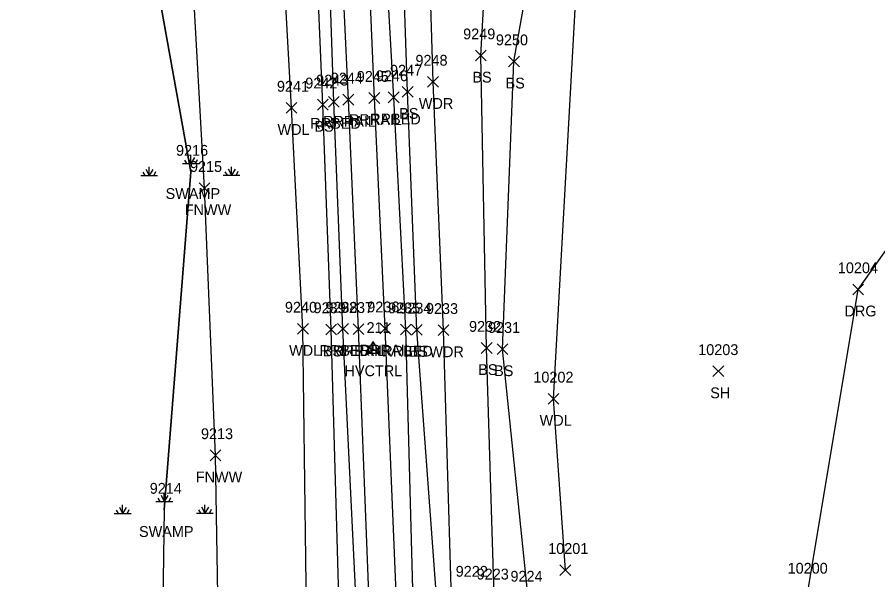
# Model space of a CAD drawing. Extents: x 1769141 to 1770911, y 735471 to 741449.
# Drawn here: x 1770233.4 to 1770392.9, y 738326.8 to 738431 of the extents above; entities that cross this region are included whole.
import ezdxf

# ---------------------------------------------------------------- set-up
doc = ezdxf.new("R2010")
doc.units = 0
for name, color, linetype in [('C_A', 7, 'Continuous'), ('C_I', 7, 'Continuous'), ('CPSM', 7, 'Continuous'), ('L_A', 7, 'Continuous'), ('L_I', 7, 'Continuous'), ('L_TIC', 7, 'Continuous'), ('LAWA', 7, 'Continuous'), ('LELB', 7, 'Continuous'), ('LFNC', 7, 'Continuous'), ('LSOGP', 7, 'Continuous'), ('LWET', 7, 'Continuous'), ('R_A', 7, 'Continuous'), ('R_I', 7, 'Continuous'), ('R_TIC', 7, 'Continuous'), ('RDG', 7, 'Continuous'), ('RR', 7, 'Continuous'), ('RRB', 7, 'Continuous'), ('U_I', 7, 'Continuous')]:
    doc.layers.add(name, color=color, linetype=linetype)

msp = doc.modelspace()

# ---------------------------------------------------------------- linework, layer by layer
at = {"layer": 'CPSM'}
for p, q in [((1770298.12, 738368.83), (1770299.37, 738371)), ((1770300.62, 738368.83), (1770299.37, 738371)), ((1770299.37, 738369.55), (1770299.37, 738371)), ((1770298.12, 738368.83), (1770299.37, 738369.55)), ((1770298.12, 738368.83), (1770300.62, 738368.83)), ((1770299.37, 738369.55), (1770299.37, 738369.55)), ((1770299.37, 738369.55), (1770300.62, 738368.83))]:
    msp.add_line(p, q, dxfattribs=at)
at = {"layer": 'L_TIC'}
for points in [[(1770318.32, 738422.93), (1770320.32, 738424.93)], [(1770320.32, 738422.93), (1770318.32, 738424.93)], [(1770324.47, 738421.83), (1770326.47, 738423.83)], [(1770326.47, 738421.83), (1770324.47, 738423.83)], [(1770309.47, 738418.05), (1770311.47, 738420.05)], [(1770311.47, 738418.05), (1770309.47, 738420.05)], [(1770304.76, 738416.21), (1770306.76, 738418.21)], [(1770306.76, 738416.21), (1770304.76, 738418.21)], [(1770283.23, 738413.23), (1770285.23, 738415.23)], [(1770285.23, 738413.23), (1770283.23, 738415.23)], [(1770289.05, 738413.83), (1770291.05, 738415.83)], [(1770291.05, 738413.83), (1770289.05, 738415.83)], [(1770267.11, 738398.37), (1770269.11, 738400.37)], [(1770269.11, 738398.37), (1770267.11, 738400.37)], [(1770285.37, 738372.32), (1770287.37, 738374.32)], [(1770287.37, 738372.32), (1770285.37, 738374.32)], [(1770290.6, 738372.21), (1770292.6, 738374.21)], [(1770292.6, 738372.21), (1770290.6, 738374.21)], [(1770306.48, 738372.15), (1770308.48, 738374.15)], [(1770308.48, 738372.15), (1770306.48, 738374.15)], [(1770311.42, 738372.07), (1770313.42, 738374.07)], [(1770313.42, 738372.07), (1770311.42, 738374.07)], [(1770319.4, 738368.77), (1770321.4, 738370.77)], [(1770321.4, 738368.77), (1770319.4, 738370.77)], [(1770322.35, 738368.56), (1770324.35, 738370.56)], [(1770324.35, 738368.56), (1770322.35, 738370.56)], [(1770362.35, 738364.46), (1770364.35, 738366.46)], [(1770364.35, 738364.46), (1770362.35, 738366.46)], [(1770331.81, 738359.37), (1770333.81, 738361.37)], [(1770333.81, 738359.37), (1770331.81, 738361.37)], [(1770269.16, 738348.89), (1770271.16, 738350.89)], [(1770271.16, 738348.89), (1770269.16, 738350.89)], [(1770333.99, 738327.63), (1770335.99, 738329.63)], [(1770335.99, 738327.63), (1770333.99, 738329.63)]]:
    msp.add_lwpolyline(points, dxfattribs=at)
at = {"layer": 'LAWA'}
for points in [[(1770290.87, 738210.89), (1770288.63, 738250.64), (1770288.03, 738279.05), (1770287.09, 738316.52), (1770286.37, 738373.32), (1770284.23, 738414.23), (1770281.88, 738456.63), (1770278.67, 738493.65), (1770276.84, 738534.04), (1770275.57, 738566.34), (1770269.92, 738609.96), (1770271.4, 738639.13), (1770266.81, 738683.22), (1770266.67, 738720.45), (1770266.46, 738767.63)], [(1770315.31, 737855.3), (1770316.28, 737876.24), (1770318.08, 737906.16), (1770319.03, 737952.94), (1770319.51, 737991.64), (1770322.73, 738039.36), (1770319.98, 738085.11), (1770320.24, 738127.38), (1770319.97, 738169.49), (1770317.68, 738213.18), (1770316.02, 738251.23), (1770320.47, 738275.34), (1770313.94, 738321.19), (1770312.42, 738373.07), (1770310.47, 738419.05), (1770309.28, 738459.52), (1770309.11, 738496.14), (1770304.45, 738533.38), (1770304.4, 738567.19), (1770302.72, 738608.9), (1770310.17, 738610.98)], [(1770334.99, 738328.63), (1770332.81, 738360.37), (1770337.6, 738446.97), (1770400.36, 738434.35)]]:
    msp.add_lwpolyline(points, dxfattribs=at)
at = {"layer": 'LELB'}
for points in [[(1770313.1, 738041.42), (1770314.65, 738083.84), (1770313.8, 738128.25), (1770314.4, 738170.05), (1770312.34, 738212.97), (1770312.21, 738250.53), (1770315.19, 738274.63), (1770311.43, 738319.54), (1770307.48, 738373.15), (1770305.76, 738417.21), (1770304.29, 738459.21), (1770301.19, 738494.77), (1770301.03, 738535.15), (1770299.09, 738567.61), (1770297.92, 738610.57), (1770296.26, 738639.11), (1770291.84, 738684.86), (1770290.03, 738722.63), (1770290.09, 738765.93)], [(1770294.4, 738212.07), (1770294.88, 738249.38), (1770293.51, 738277.71), (1770293.17, 738317.26), (1770291.6, 738373.21), (1770290.05, 738414.83), (1770288.24, 738457.21), (1770285.83, 738494.21), (1770284.22, 738534.7), (1770282.04, 738566.65), (1770280.54, 738611.07), (1770279.02, 738639.53), (1770277.04, 738683.67), (1770274.8, 738722.5), (1770272.74, 738765.19)], [(1770326.03, 738235.15), (1770326.08, 738270.84), (1770321.82, 738323.89), (1770320.4, 738369.77), (1770319.32, 738423.93), (1770321.23, 738457.95), (1770319.1, 738494.22), (1770313.73, 738532.83), (1770310.82, 738569.99), (1770306.37, 738604), (1770310.96, 738607.23)], [(1770332.56, 738233.09), (1770328.53, 738276.16), (1770328.08, 738323.5), (1770323.35, 738369.56), (1770325.47, 738422.83), (1770330.73, 738452.63), (1770331.83, 738461.72), (1770324.98, 738493.96), (1770317.4, 738534.73), (1770314.07, 738570.87), (1770310.96, 738607.23)]]:
    msp.add_lwpolyline(points, dxfattribs=at)
at = {"layer": 'LFNC'}
msp.add_lwpolyline([(1770273.27, 738043.72), (1770275.19, 738080.3), (1770274.36, 738102.02), (1770274.62, 738164.96), (1770272.85, 738219.41), (1770272.54, 738241.81), (1770271.1, 738294.49), (1770270.16, 738349.89), (1770268.11, 738399.37), (1770265.97, 738438.09), (1770263.15, 738477.86), (1770260.52, 738511.38), (1770260.81, 738538.94), (1770259.86, 738579.92), (1770256.94, 738637.73), (1770254.26, 738686.1), (1770251.71, 738756.19)], dxfattribs=at)
at = {"layer": 'LSOGP'}
msp.add_lwpolyline([(1770233.41, 738685.9), (1770237.36, 738623.37), (1770249.19, 738590.25), (1770248.16, 738546.75), (1770251.24, 738508.92), (1770248.04, 738476.27), (1770255.26, 738459.72), (1770265.59, 738402.37), (1770260.66, 738339.78), (1770259.83, 738283.89), (1770262.39, 738245.27), (1770266.4, 738210.67)], dxfattribs=at)
at = {"layer": 'LWET'}
for p, q in [((1770264.99, 738405.11), (1770265.6, 738403.94)), ((1770265.59, 738403.93), (1770265.58, 738405.51)), ((1770266.26, 738405.02), (1770265.6, 738403.94)), ((1770264.04, 738403.92), (1770267.16, 738403.94)), ((1770264.39, 738404.56), (1770264.77, 738403.92)), ((1770266.76, 738404.62), (1770266.46, 738403.94)), ((1770273.11, 738401.76), (1770273.1, 738403.34)), ((1770256.31, 738401.7), (1770259.43, 738401.72)), ((1770256.66, 738402.34), (1770257.05, 738401.7)), ((1770257.27, 738402.89), (1770257.87, 738401.72)), ((1770257.86, 738401.71), (1770257.85, 738403.29)), ((1770258.53, 738402.8), (1770257.87, 738401.72)), ((1770257.91, 738401.77), (1770257.87, 738401.77)), ((1770259.03, 738402.4), (1770258.74, 738401.72)), ((1770265.59, 738402.37), (1770265.59, 738402.37)), ((1770271.56, 738401.76), (1770274.68, 738401.77)), ((1770271.91, 738402.4), (1770272.29, 738401.76)), ((1770272.51, 738402.95), (1770273.12, 738401.77)), ((1770273.78, 738402.86), (1770273.12, 738401.77)), ((1770273.16, 738401.83), (1770273.12, 738401.83)), ((1770274.28, 738402.45), (1770273.98, 738401.77)), ((1770260.66, 738341.34), (1770260.65, 738342.92)), ((1770259.11, 738341.33), (1770262.23, 738341.35)), ((1770259.46, 738341.97), (1770259.84, 738341.33)), ((1770260.06, 738342.52), (1770260.67, 738341.35)), ((1770261.33, 738342.43), (1770260.67, 738341.35)), ((1770261.83, 738342.03), (1770261.53, 738341.35)), ((1770251.73, 738339.75), (1770252.12, 738339.11)), ((1770252.34, 738340.3), (1770252.94, 738339.13)), ((1770252.93, 738339.12), (1770252.92, 738340.7)), ((1770253.6, 738340.21), (1770252.94, 738339.13)), ((1770254.1, 738339.81), (1770253.81, 738339.13)), ((1770260.66, 738339.78), (1770260.66, 738339.78)), ((1770266.98, 738339.81), (1770267.36, 738339.16)), ((1770267.58, 738340.36), (1770268.19, 738339.18)), ((1770268.18, 738339.17), (1770268.17, 738340.75)), ((1770268.85, 738340.27), (1770268.19, 738339.18)), ((1770269.35, 738339.86), (1770269.05, 738339.18)), ((1770251.38, 738339.11), (1770254.51, 738339.13)), ((1770252.98, 738339.18), (1770252.94, 738339.18)), ((1770266.63, 738339.16), (1770269.75, 738339.18)), ((1770268.23, 738339.23), (1770268.19, 738339.23))]:
    msp.add_line(p, q, dxfattribs=at)
msp.add_lwpolyline([(1770260.66, 738339.78), (1770265.59, 738402.37), (1770255.26, 738459.72)], dxfattribs=at)
at = {"layer": 'R_TIC'}
for points in [[(1770291.07, 738414.37), (1770293.07, 738416.37)], [(1770293.07, 738414.37), (1770291.07, 738416.37)], [(1770293.78, 738414.75), (1770295.78, 738416.75)], [(1770295.78, 738414.75), (1770293.78, 738416.75)], [(1770298.6, 738415.06), (1770300.6, 738417.06)], [(1770300.6, 738415.06), (1770298.6, 738417.06)], [(1770302.18, 738415.18), (1770304.18, 738417.18)], [(1770304.18, 738415.18), (1770302.18, 738417.18)], [(1770388.24, 738379.62), (1770390.24, 738381.62)], [(1770390.24, 738379.62), (1770388.24, 738381.62)], [(1770292.78, 738372.31), (1770294.78, 738374.31)], [(1770294.78, 738372.31), (1770292.78, 738374.31)], [(1770295.67, 738372.26), (1770297.67, 738374.26)], [(1770297.67, 738372.26), (1770295.67, 738374.26)], [(1770300.59, 738372.37), (1770302.59, 738374.37)], [(1770302.59, 738372.37), (1770300.59, 738374.37)], [(1770304.41, 738372.19), (1770306.41, 738374.19)], [(1770306.41, 738372.19), (1770304.41, 738374.19)]]:
    msp.add_lwpolyline(points, dxfattribs=at)
at = {"layer": 'RDG'}
msp.add_lwpolyline([(1770421.77, 738317.22), (1770380.02, 738324.98), (1770389.24, 738380.62), (1770403.72, 738400.98), (1770422.62, 738412.18), (1770438.53, 738414.48), (1770453.78, 738413.3), (1770513.31, 738409.59), (1770526.11, 738411.83)], dxfattribs=at)
at = {"layer": 'RR'}
for points in [[(1770306.83, 738212.61), (1770305.97, 738251.61), (1770305.45, 738274.73), (1770303.86, 738318.41), (1770301.59, 738373.37), (1770299.6, 738416.06), (1770297.81, 738458.2), (1770295.91, 738494.23), (1770293.95, 738535.47), (1770292.37, 738567.24), (1770290.33, 738610.79), (1770288.95, 738639.29), (1770286.62, 738684.53), (1770284.78, 738722.44), (1770282.75, 738765.34), (1770281.81, 738782.62), (1770280.63, 738807.93), (1770278.94, 738841.61), (1770277.73, 738864.84), (1770275.76, 738907.17), (1770272.82, 738964.46), (1770270.62, 739009.24), (1770268.25, 739059.17)], [(1770301.97, 738212.47), (1770301.09, 738251.23), (1770300.45, 738274.52), (1770298.83, 738317.94), (1770296.67, 738373.26), (1770294.78, 738415.75), (1770292.82, 738457.58), (1770291.14, 738493.74), (1770289.07, 738535.25), (1770287.55, 738567.14), (1770285.28, 738610.63), (1770283.97, 738639.09), (1770281.79, 738684.17), (1770279.94, 738722.46), (1770277.74, 738764.73), (1770276.79, 738782.67), (1770275.73, 738808.22), (1770274.1, 738841.5), (1770272.9, 738864.68), (1770270.88, 738905.77), (1770268.08, 738963.97), (1770265.55, 739008.76), (1770263.29, 739058.54)]]:
    msp.add_lwpolyline(points, dxfattribs=at)
at = {"layer": 'RRB'}
for points in [[(1770309.73, 738212.86), (1770310.49, 738250.9), (1770309.26, 738275.06), (1770306.88, 738318.18), (1770305.41, 738373.19), (1770303.18, 738416.18), (1770300.79, 738458.59), (1770298.49, 738494.01), (1770297.04, 738536.46), (1770294.86, 738567.22), (1770292.96, 738610.45), (1770291.98, 738639.65), (1770289.94, 738684.66), (1770287.49, 738722.38), (1770286.38, 738765.8), (1770285.58, 738776.55), (1770285.43, 738783.69), (1770283.4, 738807.76), (1770281.94, 738841.39), (1770280.11, 738864.76), (1770278.71, 738907.77), (1770276.02, 738964.78), (1770273.87, 739009.57), (1770271.43, 739060.03)], [(1770299.07, 738212.61), (1770298.2, 738250.42), (1770297.38, 738275.96), (1770296.49, 738317.49), (1770293.78, 738373.31), (1770292.07, 738415.37), (1770290.67, 738457.61), (1770288.25, 738494.03), (1770286.88, 738535.11), (1770284.37, 738566.9), (1770283.35, 738611.08), (1770281.22, 738639.28), (1770279.31, 738683.92), (1770276.99, 738722.67), (1770274.83, 738764.68), (1770274.02, 738775.85), (1770273.59, 738782.27), (1770272.75, 738808.4), (1770271.58, 738841.7), (1770269.95, 738864.96), (1770268.23, 738905.19), (1770264.82, 738963.75), (1770263.31, 739007.85), (1770260.59, 739058.13)]]:
    msp.add_lwpolyline(points, dxfattribs=at)

# ---------------------------------------------------------------- texts
at = {"layer": 'C_A'}
msp.add_text('HVCTRL', height=2, dxfattribs=at).set_placement((1770294.07, 738364.55))
at = {"layer": 'C_I'}
msp.add_text('211', height=2, dxfattribs=at).set_placement((1770298.15, 738372.55))
at = {"layer": 'L_A'}
for s, p in [('BS', (1770317.76, 738418.93)), ('BS', (1770323.91, 738417.83)), ('WDR', (1770307.84, 738414.05)), ('BS', (1770304.2, 738412.21)), ('BS', (1770288.49, 738409.83)), ('WDL', (1770281.65, 738409.23)), ('SWAMP', (1770260.91, 738397.37)), ('FNWW', (1770264.46, 738394.37)), ('WDL', (1770283.79, 738368.32)), ('BS', (1770290.04, 738368.21)), ('BS', (1770305.92, 738368.15)), ('WDR', (1770309.78, 738368.07)), ('BS', (1770318.84, 738364.77)), ('BS', (1770321.79, 738364.56)), ('SH', (1770361.84, 738360.46)), ('WDL', (1770330.22, 738355.37)), ('FNWW', (1770266.5, 738344.89)), ('SWAMP', (1770255.98, 738334.78))]:
    msp.add_text(s, height=2, dxfattribs=at).set_placement(p)
at = {"layer": 'L_I'}
for s, p in [('9249', (1770316.05, 738426.93)), ('9250', (1770322.12, 738425.83)), ('9248', (1770307.21, 738422.05)), ('9247', (1770302.5, 738420.21)), ('9241', (1770281.54, 738417.23)), ('9242', (1770286.79, 738417.83)), ('9216', (1770262.84, 738405.37)), ('9215', (1770265.42, 738402.37)), ('9240', (1770283.02, 738376.32)), ('9239', (1770288.33, 738376.21)), ('9234', (1770304.22, 738376.15)), ('9233', (1770309.16, 738376.07)), ('9232', (1770317.14, 738372.77)), ('9231', (1770320.66, 738372.56)), ('10203', (1770359.61, 738368.46)), ('10202', (1770329.06, 738363.37)), ('9213', (1770267.46, 738352.89)), ('9214', (1770257.97, 738342.78)), ('10201', (1770331.81, 738331.63)), ('9223', (1770318.56, 738326.89)), ('9224', (1770324.82, 738326.5))]:
    msp.add_text(s, height=2, dxfattribs=at).set_placement(p)
at = {"layer": 'R_A'}
for s, p in [('RRRAIL', (1770294.89, 738411.06)), ('RRBED', (1770298.83, 738411.18)), ('RRBED', (1770287.72, 738410.37)), ('RRRAIL', (1770290.08, 738410.75)), ('DRG', (1770386.72, 738375.62)), ('RRBED', (1770289.43, 738368.31)), ('RRRAIL', (1770291.96, 738368.26)), ('RRRAIL', (1770296.88, 738368.37)), ('RRBED', (1770301.06, 738368.19))]:
    msp.add_text(s, height=2, dxfattribs=at).set_placement(p)
at = {"layer": 'R_I'}
for s, p in [('9245', (1770296.34, 738419.06)), ('9246', (1770299.87, 738419.18)), ('9243', (1770288.81, 738418.37)), ('9244', (1770291.52, 738418.75)), ('10204', (1770385.49, 738383.62)), ('9238', (1770290.52, 738376.31)), ('9237', (1770293.41, 738376.26)), ('9236', (1770298.27, 738376.37)), ('9235', (1770302.15, 738376.19)), ('10200', (1770376.18, 738327.98))]:
    msp.add_text(s, height=2, dxfattribs=at).set_placement(p)
at = {"layer": 'U_I'}
msp.add_text('9222', height=2, dxfattribs=at).set_placement((1770314.67, 738327.41))

doc.saveas('drawing.dxf')
